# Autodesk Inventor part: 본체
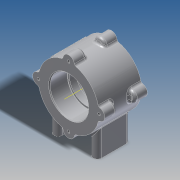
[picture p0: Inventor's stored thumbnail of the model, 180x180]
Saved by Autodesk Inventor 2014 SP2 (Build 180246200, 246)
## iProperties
Created: 2015-03
Part Number: 본체
Material: 알루미늄 6061
Document SubType Name: Modeling
Designer: 201-07
Mass: 448.938 g
Surface Area: 330.888 cm^2
Volume: 165.66 cm^3
Density: 2.71 g/cm^3
Appearance: 알루미늄 - 평지
Author: 201-07
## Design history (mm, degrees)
sketch "스케치1"
  geometry: C1 r 37 at (0, 0); 1 further point
  constraints: 1 centre point, 1 coincident
  dimensions: "d0" = 74 diameter of C1
extrude "돌출1" new body sketch "스케치1" stored distance "d1" = 52; taper "d2" = 0 deg
sketch "스케치2"
  geometry: C1 r 7 at (0, 37); 1 further point
  constraints: 2 vertical alignment, 1 centre point, 1 other
  dimensions: "d3" = 14 diameter of C1
extrude "돌출2" join sketch "스케치2" distance "d4" = 15; taper "d5" = 0 deg
fillet "모깎기1" dims "d6" = 3
sketch "스케치3"
  geometry: L1 (-29, -14.37)-(-19, -14.37); L2 (-19, -14.37)-(-19, -56); L3 (-19, -56)-(-29, -56); L4 (-29, -56)-(-29, -14.37); L5 (-24, -56)-(-24, -14.37); 1 further point
  constraints: 10 end point, 2 midpoint, 2 parallel, 1 horizontal, 1 perpendicular
  dimensions: "d10" = 56 distance from line of L3 point (0, 0); "d11" = 10 distance of L2.end L3.end; "d12" = 24 horizontal distance of L5.start point (0, 0)
extrude "돌출3" join sketch "스케치3" stored distance "d13" = 40; taper "d14" = 0 deg
fillet "모깎기2" dims "d15" = 5
fillet "모깎기3" dims "d16" = 3
sketch "스케치4"
  geometry: A1 r 5 centre (0, 0) between (-5, 0) and (5, 0) reference; A2 r 5 centre (0, 30) between (5, 30) and (-5, 30) reference; 1 further point
hole "구멍1" sketch "스케치4" at (0, 30), (0, 0) diameter "d17" = 4.134; stored, may be unused: countersink angle "d21" = 82 deg, drill point angle "d23" = 118 deg; dims "d18" = 6, "d19" = 3.023, "d20" = 2, "d22" = 8
sketch "스케치5"
  geometry: A1 r 7 centre (0, 37) between (6.889, 38.239) and (-6.889, 38.239) reference; A2 r 7 centre (-37, 0) between (-38.239, 6.889) and (-38.239, -6.889) reference; A3 r 7 centre (0, -37) between (-6.889, -38.239) and (6.889, -38.239) reference; A4 r 7 centre (37, 0) between (38.239, -6.889) and (38.239, 6.889) reference
hole "구멍2" sketch "스케치5" at (0, 37), (-37, 0), (37, 0), (0, -37) diameter "d24" = 3.242; stored, may be unused: countersink angle "d28" = 82 deg, drill point angle "d30" = 118 deg; dims "d25" = 8, "d26" = 3.023, "d27" = 2, "d29" = 11
hole "구멍3" diameter "d33" = 42; stored, may be unused: countersink angle "d37" = 82 deg, drill point angle "d39" = 0 deg; dims "d34" = 8, "d35" = 3.023, "d36" = 2, "d38" = 11, "d42" = 10, "d43" = 10
hole "구멍4" diameter "d44" = 47; stored, may be unused: countersink angle "d48" = 82 deg, drill point angle "d50" = 0 deg; dims "d40" = 10, "d41" = 10, "d45" = 8, "d46" = 3.023, "d47" = 2, "d49" = 22
hole "구멍5" diameter "d53" = 47; stored, may be unused: countersink angle "d57" = 82 deg, drill point angle "d59" = 0 deg; dims "d51" = 10, "d52" = 10, "d54" = 8, "d55" = 3.023, "d56" = 2, "d58" = 22
fillet "모깎기4" dims "d60" = 0.3
chamfer "모따기1" distance "d61" = 1; stored, may be unused: second distance "d62" = 2, angle "d63" = 45 deg
node "작업 평면3"
  node "작업 평면2"
sketch "스케치6"
  geometry: L1 (-3.002, -20.739)-(-3.002, 20.739); L2 (-3.002, 20.739)-(3.002, 20.739); L3 (3.002, 20.739)-(3.002, -20.739); L4 (3.002, -20.739)-(-3.002, -20.739); 3 further points
  constraints: 2 midpoint, 1 horizontal alignment, 1 vertical alignment, 2 other
feature "엠보싱1" sketch "스케치6" dims "d10" = 56, "d11" = 10, "d12" = 24, "d65" = 0.5, "d66" = 0
node "솔리드1"
pattern_circular "원형 패턴1" dims angle "d8" = 360 deg
mirror "대칭1"
mirror "대칭2"
mirror "대칭3"
node "작업 평면1"
node "작업축1"
other parameters: "d64" = -45 deg
